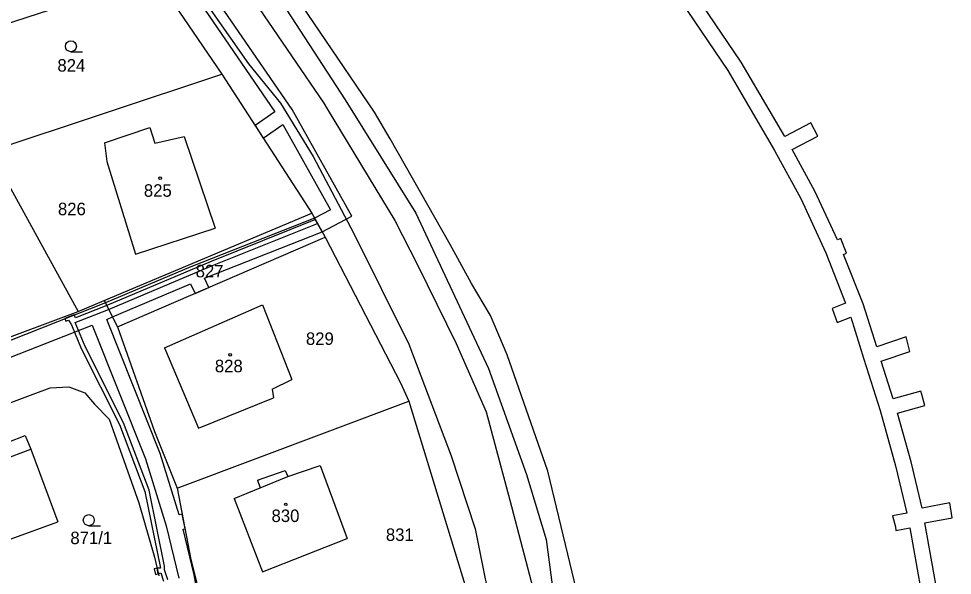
# Model space of a CAD drawing. Extents: x -785744 to -782822, y -1067550 to -1063910.
# Drawn here: x -783459.2 to -783332.2, y -1066254.8 to -1066179.1 of the extents above; entities that cross this region are included whole.
import ezdxf

# ---------------------------------------------------------------- set-up
doc = ezdxf.new("R2010")
doc.units = 0
for name, color, linetype in [('Hranice kat_území', 7, 'Continuous'), ('Hranice parcel', 7, 'Continuous'), ('Parcelní čísla', 7, 'Continuous'), ('Vnitřní kresba', 7, 'Continuous'), ('Věcná břemena k části', 7, 'Continuous'), ('Značky budov', 7, 'Continuous'), ('Značky kultur', 7, 'Continuous')]:
    doc.layers.add(name, color=color, linetype=linetype)

msp = doc.modelspace()

# ---------------------------------------------------------------- linework, layer by layer
at = {"layer": 'Hranice kat_území'}
msp.add_lwpolyline([(-783403.72, -1066520.48), (-783408.95, -1066445.43), (-783408.98, -1066441.05), (-783406.06, -1066440.89), (-783397.12, -1066388.66), (-783396.74, -1066386.18), (-783395.27, -1066375.27), (-783394.46, -1066371.28), (-783389.04, -1066341.47), (-783386.35, -1066325.72), (-783383.12, -1066306.7), (-783381.34, -1066290.13), (-783381.25, -1066273.33), (-783383.32, -1066256.79), (-783387.23, -1066240.6), (-783392.79, -1066224.78), (-783395.02, -1066219.44), (-783397.61, -1066215.1), (-783400.51, -1066209.79), (-783408.68, -1066195.43), (-783410.8, -1066191.77), (-783425.61, -1066169.96)], dxfattribs=at)
at = {"layer": 'Hranice parcel'}
for points in [[(-783435.32, -1066164.77), (-783417.71, -1066190.54)], [(-783440.65, -1066173.27), (-783431.59, -1066186.6)], [(-783470.99, -1066183.03), (-783453.33, -1066177.34)], [(-783463.17, -1066197.11), (-783431.59, -1066186.6)], [(-783431.59, -1066186.6), (-783419.34, -1066205.52)], [(-783417.71, -1066190.54), (-783417.28, -1066191.31)], [(-783417.28, -1066191.31), (-783408.07, -1066206.51)], [(-783447.57, -1066195.95), (-783441.39, -1066193.85)], [(-783441.39, -1066193.85), (-783440.73, -1066195.98)], [(-783440.73, -1066195.98), (-783436.72, -1066195.1)], [(-783436.72, -1066195.1), (-783432.49, -1066207.54)], [(-783447.57, -1066195.95), (-783447.23, -1066198.51)], [(-783463.17, -1066197.11), (-783451.13, -1066218.9)], [(-783447.23, -1066198.51), (-783443.36, -1066211.11)], [(-783447.59, -1066217.42), (-783419.34, -1066205.52)], [(-783419.34, -1066205.52), (-783417.54, -1066208.78)], [(-783408.07, -1066206.51), (-783404.97, -1066212.54)], [(-783443.36, -1066211.11), (-783432.49, -1066207.54)], [(-783445.79, -1066221), (-783417.54, -1066208.78)], [(-783417.54, -1066208.78), (-783407.3, -1066228.59)], [(-783404.97, -1066212.54), (-783399.73, -1066223.23)], [(-783451.13, -1066218.9), (-783447.59, -1066217.42)], [(-783447.59, -1066217.42), (-783445.79, -1066221)], [(-783439.38, -1066223.86), (-783426.07, -1066218)], [(-783426.07, -1066218), (-783422.06, -1066228.16)], [(-783474.85, -1066227.74), (-783451.13, -1066218.9)], [(-783445.79, -1066221), (-783440.77, -1066235.21)], [(-783399.73, -1066223.23), (-783395.63, -1066232.55)], [(-783439.38, -1066223.86), (-783434.77, -1066234.75)], [(-783424.75, -1066229.45), (-783422.06, -1066228.16)], [(-783457.28, -1066230.16), (-783454.95, -1066229.26)], [(-783454.95, -1066229.26), (-783452.39, -1066229.13)], [(-783452.39, -1066229.13), (-783450.24, -1066229.95)], [(-783424.75, -1066229.45), (-783424.56, -1066230.62)], [(-783407.3, -1066228.59), (-783406.15, -1066231.09)], [(-783475.82, -1066237.06), (-783457.28, -1066230.16)], [(-783450.24, -1066229.95), (-783448.9, -1066231.49)], [(-783437.65, -1066242.91), (-783406.15, -1066231.09)], [(-783434.77, -1066234.75), (-783424.56, -1066230.62)], [(-783406.15, -1066231.09), (-783398.51, -1066256.04)], [(-783448.9, -1066231.49), (-783446.92, -1066233.55)], [(-783446.92, -1066233.55), (-783442.87, -1066244.94)], [(-783395.63, -1066232.55), (-783392.39, -1066244.54)], [(-783460.67, -1066236.69), (-783458.36, -1066235.74)], [(-783458.36, -1066235.74), (-783457.6, -1066237.6)], [(-783440.77, -1066235.21), (-783437.65, -1066242.91)], [(-783457.6, -1066237.6), (-783453.9, -1066247.51)], [(-783422.63, -1066241.36), (-783418.22, -1066239.84)], [(-783418.22, -1066239.84), (-783414.52, -1066249.79)], [(-783426.72, -1066241.84), (-783422.99, -1066240.51)], [(-783422.99, -1066240.51), (-783422.63, -1066241.36)], [(-783426.72, -1066241.84), (-783426.37, -1066242.87)], [(-783437.65, -1066242.91), (-783435.79, -1066252.61)], [(-783429.91, -1066244.35), (-783426.37, -1066242.87)], [(-783442.87, -1066244.94), (-783440.75, -1066252.32)], [(-783429.91, -1066244.35), (-783426.05, -1066254.31)], [(-783392.39, -1066244.54), (-783389.01, -1066257.54)], [(-783466.3, -1066251.98), (-783453.9, -1066247.51)], [(-783426.05, -1066254.31), (-783414.52, -1066249.79)], [(-783440.75, -1066252.32), (-783440.18, -1066254.85)], [(-783435.79, -1066252.61), (-783432.9, -1066264.14)]]:
    msp.add_lwpolyline(points, dxfattribs=at)
at = {"layer": 'Vnitřní kresba'}
for points in [[(-783441.17, -1066149.59), (-783414.82, -1066190.09)], [(-783446.94, -1066158.13), (-783427.97, -1066185.2)], [(-783427.97, -1066185.2), (-783423.63, -1066190.56)], [(-783414.82, -1066190.09), (-783405.18, -1066205.51)], [(-783423.63, -1066190.56), (-783419.18, -1066197.8)], [(-783419.18, -1066197.8), (-783413.65, -1066208.3)], [(-783405.18, -1066205.51), (-783395.29, -1066226.64)], [(-783413.65, -1066208.3), (-783406.13, -1066223.33)], [(-783406.13, -1066223.33), (-783400.4, -1066238.55)], [(-783395.29, -1066226.64), (-783390.12, -1066241.05)], [(-783461.45, -1066239.09), (-783457.6, -1066237.6)], [(-783400.4, -1066238.55), (-783397.12, -1066248.45)], [(-783390.12, -1066241.05), (-783387.45, -1066249.91)], [(-783426.37, -1066242.87), (-783422.63, -1066241.36)], [(-783397.12, -1066248.45), (-783394.3, -1066262.48)], [(-783387.45, -1066249.91), (-783385.12, -1066267.72)]]:
    msp.add_lwpolyline(points, dxfattribs=at)
at = {"layer": 'Věcná břemena k části'}
for points in [[(-783360.92, -1066184.97), (-783368.01, -1066174.5)], [(-783422.02, -1066191.4), (-783432.21, -1066176.59)], [(-783369.15, -1066176.68), (-783362.74, -1066186.13)], [(-783433.95, -1066177.79), (-783424.37, -1066191.72)], [(-783355, -1066195.11), (-783360.92, -1066184.97)], [(-783362.74, -1066186.13), (-783356.38, -1066197.02)], [(-783424.37, -1066191.72), (-783427.07, -1066193.58)], [(-783413.89, -1066205.91), (-783422.02, -1066191.4)], [(-783427.07, -1066193.58), (-783425.96, -1066195.3)], [(-783425.96, -1066195.3), (-783423.3, -1066193.46)], [(-783423.3, -1066193.46), (-783416.79, -1066205.07)], [(-783351.45, -1066193.24), (-783355, -1066195.11)], [(-783350.5, -1066195.05), (-783351.45, -1066193.24)], [(-783353.99, -1066196.88), (-783350.5, -1066195.05)], [(-783356.38, -1066197.02), (-783352.82, -1066203.53)], [(-783350.9, -1066202.55), (-783353.99, -1066196.88)], [(-783347.83, -1066209.17), (-783350.9, -1066202.55)], [(-783352.82, -1066203.53), (-783349.4, -1066210.94)], [(-783416.79, -1066205.07), (-783418.97, -1066206.18)], [(-783418.97, -1066206.18), (-783435.79, -1066212.82)], [(-783418.87, -1066206.37), (-783433.06, -1066212.08)], [(-783432.84, -1066212.64), (-783418.57, -1066206.91)], [(-783417.94, -1066208.05), (-783418.97, -1066206.18)], [(-783418.97, -1066206.18), (-783417.94, -1066208.05)], [(-783418.57, -1066206.91), (-783418.87, -1066206.37)], [(-783417.94, -1066208.05), (-783413.89, -1066205.91)], [(-783433.97, -1066214.38), (-783417.94, -1066208.05)], [(-783347.36, -1066208.99), (-783347.83, -1066209.17)], [(-783346.61, -1066210.97), (-783347.36, -1066208.99)], [(-783349.4, -1066210.94), (-783346.75, -1066217.75)], [(-783347.01, -1066211.13), (-783346.61, -1066210.97)], [(-783344.34, -1066217.85), (-783347.01, -1066211.13)], [(-783435.79, -1066212.82), (-783447.43, -1066217.74)], [(-783433.06, -1066212.08), (-783447.26, -1066218.07)], [(-783446.99, -1066218.61), (-783432.84, -1066212.64)], [(-783433.36, -1066215.63), (-783433.97, -1066214.38)], [(-783446.47, -1066219.64), (-783435.86, -1066215.15)], [(-783435.86, -1066215.15), (-783435.24, -1066216.44)], [(-783435.24, -1066216.44), (-783433.36, -1066215.63)], [(-783447.43, -1066217.74), (-783467.06, -1066225.48)], [(-783447.26, -1066218.07), (-783451.52, -1066219.74)], [(-783346.75, -1066217.75), (-783348.55, -1066218.49)], [(-783342.49, -1066223.71), (-783344.34, -1066217.85)], [(-783451.68, -1066219.34), (-783452.96, -1066219.83)], [(-783451.52, -1066219.74), (-783451.68, -1066219.34)], [(-783451.54, -1066220.4), (-783446.99, -1066218.61)], [(-783447.26, -1066219.97), (-783446.47, -1066219.64)], [(-783348.55, -1066218.49), (-783347.88, -1066220.41)], [(-783347.88, -1066220.41), (-783346.03, -1066219.66)], [(-783346.03, -1066219.66), (-783344.24, -1066225.36)], [(-783465.32, -1066227.08), (-783449.23, -1066220.77)], [(-783452.96, -1066219.83), (-783452.82, -1066220.2)], [(-783452.82, -1066220.2), (-783452.45, -1066220.06)], [(-783452.45, -1066220.06), (-783452.06, -1066220.7)], [(-783452.06, -1066220.7), (-783450.72, -1066223.93)], [(-783450.18, -1066223.67), (-783451.54, -1066220.4)], [(-783449.23, -1066220.77), (-783441.98, -1066238.93)], [(-783439.98, -1066238.23), (-783447.26, -1066219.97)], [(-783338.46, -1066222.34), (-783342.49, -1066223.71)], [(-783337.96, -1066224.32), (-783338.46, -1066222.34)], [(-783450.72, -1066223.93), (-783445.51, -1066234.27)], [(-783444.95, -1066234.03), (-783450.18, -1066223.67)], [(-783341.88, -1066225.65), (-783337.96, -1066224.32)], [(-783344.24, -1066225.36), (-783342.01, -1066232.35)], [(-783340.24, -1066230.77), (-783341.88, -1066225.65)], [(-783336.47, -1066229.72), (-783340.24, -1066230.77)], [(-783336.33, -1066230.2), (-783336.47, -1066229.72)], [(-783335.94, -1066231.69), (-783336.33, -1066230.2)], [(-783342.01, -1066232.35), (-783339.92, -1066239.89)], [(-783339.66, -1066232.73), (-783335.94, -1066231.69)], [(-783337.82, -1066239.35), (-783339.66, -1066232.73)], [(-783445.51, -1066234.27), (-783442.07, -1066243.36)], [(-783441.49, -1066243.2), (-783444.95, -1066234.03)], [(-783437.4, -1066246.55), (-783439.98, -1066238.23)], [(-783441.98, -1066238.93), (-783439.15, -1066248.03)], [(-783339.92, -1066239.89), (-783338.37, -1066246.31)], [(-783336.31, -1066245.63), (-783337.82, -1066239.35)], [(-783442.07, -1066243.36), (-783439.93, -1066253.79)], [(-783439.37, -1066253.55), (-783441.49, -1066243.2)], [(-783332.53, -1066244.93), (-783336.31, -1066245.63)], [(-783332.2, -1066246.94), (-783332.53, -1066244.93)], [(-783338.37, -1066246.31), (-783340.35, -1066246.69)], [(-783436.97, -1066246.45), (-783437.4, -1066246.55)], [(-783436.59, -1066248.46), (-783436.97, -1066246.45)], [(-783340.35, -1066246.69), (-783339.95, -1066248.2)], [(-783335.93, -1066247.63), (-783332.2, -1066246.94)], [(-783439.15, -1066248.03), (-783437.42, -1066255.15)], [(-783436.85, -1066248.51), (-783436.59, -1066248.46)], [(-783435.34, -1066254.71), (-783436.85, -1066248.51)], [(-783339.95, -1066248.2), (-783339.88, -1066248.68)], [(-783339.88, -1066248.68), (-783338, -1066248.32)], [(-783338, -1066248.32), (-783335.48, -1066262.38)], [(-783333.16, -1066263.06), (-783335.93, -1066247.63)], [(-783440.41, -1066253.81), (-783440.81, -1066253.9)], [(-783440.81, -1066253.9), (-783440.63, -1066254.68)], [(-783439.93, -1066253.79), (-783440.41, -1066253.81)], [(-783440.41, -1066253.81), (-783440.24, -1066254.59)], [(-783440.24, -1066254.59), (-783440.41, -1066253.81)], [(-783439.41, -1066254.04), (-783439.37, -1066253.55)], [(-783440.63, -1066254.68), (-783440.24, -1066254.59)], [(-783440.24, -1066254.59), (-783439.89, -1066254.46)], [(-783439.89, -1066254.46), (-783439.51, -1066255.57)], [(-783438.93, -1066255.41), (-783439.41, -1066254.04)], [(-783432.93, -1066268.02), (-783435.34, -1066254.71)]]:
    msp.add_lwpolyline(points, dxfattribs=at)
at = {"layer": 'Značky budov'}
for centre in [(-783439.98, -1066200.77), (-783430.46, -1066224.8), (-783422.9, -1066245.12)]:
    msp.add_circle(centre, 0.175, dxfattribs=at)
at = {"layer": 'Značky kultur'}
for p, q in [((-783452.13, -1066183.57), (-783450.53, -1066183.57)), ((-783449.69, -1066248.03), (-783448.09, -1066248.03))]:
    msp.add_line(p, q, dxfattribs=at)
for centre in [(-783452.13, -1066182.82), (-783449.69, -1066247.28)]:
    msp.add_circle(centre, 0.75, dxfattribs=at)

# ---------------------------------------------------------------- texts
at = {"layer": 'Parcelní čísla'}
for s, p in [('824', (-783453.96, -1066186.27)), ('825', (-783442.2, -1066203.29)), ('826', (-783453.89, -1066205.8)), ('827', (-783435.15, -1066214.25)), ('829', (-783420.15, -1066223.44)), ('828', (-783432.54, -1066227.16)), ('830', (-783424.83, -1066247.53)), ('871/1', (-783452.2, -1066250.54)), ('831', (-783409.27, -1066250.1))]:
    msp.add_text(s, height=1.7, dxfattribs=at).set_placement(p)

doc.saveas('drawing.dxf')
